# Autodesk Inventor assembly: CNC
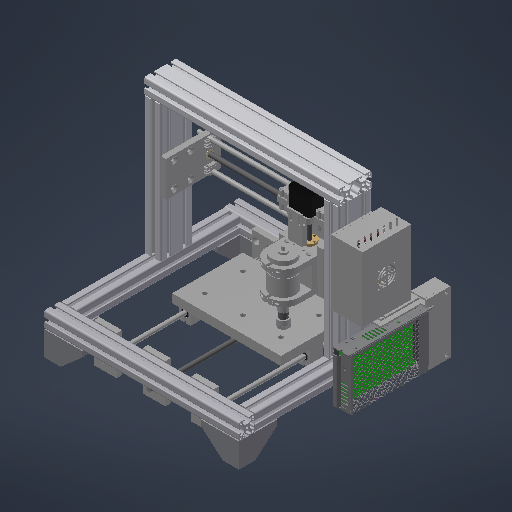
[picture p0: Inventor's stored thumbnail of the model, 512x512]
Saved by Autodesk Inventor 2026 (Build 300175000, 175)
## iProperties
Created: 2025-04
Part Number: CNC
Material: Generisch
Document SubType Name: Assembly
Designer: BennF
Author: BennF
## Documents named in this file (14)
- C:\Users\BennF\Nextcloud\Benedikt\FabAcademy\week12\CAD\CNC.iam
- C:\Users\BennF\Nextcloud\Benedikt\FabAcademy\week12\CAD\x-axis\x-axis.iam
- C:\Users\BennF\Nextcloud\Benedikt\FabAcademy\week12\CAD\z-axis\z-axis.iam
- C:\Users\BennF\Nextcloud\Benedikt\FabAcademy\week12\CAD\frame\frame.iam
- C:\Users\BennF\Nextcloud\Benedikt\FabAcademy\week12\CAD\y-axis\y-axis.iam
- C:\Users\BennF\Nextcloud\Benedikt\FabAcademy\week12\CAD\end_switch_holder_xy.ipt
- C:\Users\BennF\Nextcloud\Benedikt\FabAcademy\week12\CAD\end_switch_moc.ipt
- C:\Users\BennF\Nextcloud\Benedikt\FabAcademy\week12\CAD\electronics\RepRap\RepRap.iam
- C:\Users\BennF\Nextcloud\Benedikt\FabAcademy\week12\CAD\electronics\reprap_mounting_plate.ipt
- C:\Users\BennF\Nextcloud\Benedikt\FabAcademy\week12\CAD\electronics\LRS-150(230808)\LRS-150(230808).iam
- C:\Users\BennF\Nextcloud\Benedikt\FabAcademy\week12\CAD\electronics\psu_mounting_plate.ipt
- C:\Users\BennF\Nextcloud\Benedikt\FabAcademy\week12\CAD\electronics\psu_cover.ipt
- C:\Users\BennF\Nextcloud\Benedikt\FabAcademy\week12\CAD\electronics\reprap_cover.ipt
- C:\Users\BennF\Nextcloud\Benedikt\FabAcademy\week12\CAD\electronics\fan_mockup.ipt
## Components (15 placed, 13 different names)
1. frame:1 [sub-assembly]
2. x-axis:1 [sub-assembly] — Insert:1, Insert:2, Mate:1, Flush:1, Mate:7, Flush:5
3. z-axis:1 [sub-assembly] — Insert:1, Insert:2
4. y-axis:1 [sub-assembly] — Mate:2, Flush:2, Mate:3, Mate:5
5. end_switch_holder_xy:1 — Insert:3, Insert:4, Mate:4, Mate:5, Flush:3
6. end_switch_holder_xy:2 — Insert:5, Insert:6, Mate:6, Mate:7, Flush:4
7. end_switch_moc:1 — Insert:3, Insert:4
8. end_switch_moc:2 — Insert:5, Insert:6
9. RepRap:1 [sub-assembly] — Insert:7
10. reprap_mounting_plate:1 — Mate:8, Insert:7, Flush:8, Insert:10, Insert:11
11. LRS-150(230808):1 [sub-assembly] — Insert:8
12. psu_mounting_plate:1 — Mate:9, Flush:9, Insert:8, Flush:10, Flush:11, Flush:12, Mate:10
13. psu_cover:1 — Flush:11, Flush:12, Mate:10
14. reprap_cover:1 — Insert:9, Insert:10, Insert:11
15. fan_mockup:1 — Insert:9
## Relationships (31: Insert 11, Mate 10, Flush 10)
- Insert:1: x-axis:1 ↔ z-axis:1
- Insert:2: x-axis:1 ↔ z-axis:1
- Mate:1: x-axis:1
- Flush:1: x-axis:1
- Mate:2: y-axis:1
- Flush:2: y-axis:1
- Mate:3: y-axis:1
- Insert:3: end_switch_holder_xy:1 ↔ end_switch_moc:1
- Insert:4: end_switch_holder_xy:1 ↔ end_switch_moc:1
- Insert:5: end_switch_holder_xy:2 ↔ end_switch_moc:2
- Insert:6: end_switch_holder_xy:2 ↔ end_switch_moc:2
- Mate:4: end_switch_holder_xy:1
- Mate:5: y-axis:1 ↔ end_switch_holder_xy:1
- Flush:3: end_switch_holder_xy:1
- Mate:6: end_switch_holder_xy:2
- Mate:7: x-axis:1 ↔ end_switch_holder_xy:2
- Flush:4: end_switch_holder_xy:2
- Flush:5: x-axis:1
- Mate:8: reprap_mounting_plate:1
- Insert:7: RepRap:1 ↔ reprap_mounting_plate:1
- Flush:8: reprap_mounting_plate:1
- Mate:9: psu_mounting_plate:1
- Flush:9: psu_mounting_plate:1
- Insert:8: LRS-150(230808):1 ↔ psu_mounting_plate:1
- Flush:10: psu_mounting_plate:1
- Flush:11: psu_mounting_plate:1 ↔ psu_cover:1
- Flush:12: psu_mounting_plate:1 ↔ psu_cover:1
- Mate:10: psu_mounting_plate:1 ↔ psu_cover:1
- Insert:9: reprap_cover:1 ↔ fan_mockup:1
- Insert:10: reprap_mounting_plate:1 ↔ reprap_cover:1
- Insert:11: reprap_mounting_plate:1 ↔ reprap_cover:1
